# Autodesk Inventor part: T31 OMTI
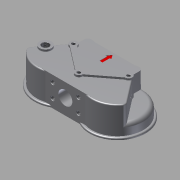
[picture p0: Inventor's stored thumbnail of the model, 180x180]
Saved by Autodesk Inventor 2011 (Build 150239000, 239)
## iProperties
Created: 2014-12
Part Number: T31 OMTI
Document SubType Name: Modeling
Designer: Храмов
Density: 1 g/cm^3
Author: Храмов
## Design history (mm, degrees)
sketch "Эскиз1"
  geometry: L1 (0, 0)-(150, 0); L2 (20.273, 67)-(129.727, 67); L3 (129.727, 67)-(129.727, -67); L4 (129.727, -67)-(20.273, -67); L5 (20.273, -67)-(20.273, 67); A1 r 70 centre (0, 0) between (-70, 0) and (20.273, 67); A2 r 70 centre (150, 0) between (220, 0) and (129.727, 67); 1 further point
  constraints: 10 end point, 4 point on circle, 2 centre point, 2 coincident, 2 horizontal, 2 parallel, 1 perpendicular
  dimensions: "d0" = 140 diameter of A1; "d1" = 140 diameter of A2; "d5" = 150 distance of A2.centre L1.start; "d6" = 67 distance between parallel lines of L2 L1; "d7" = 134 distance between parallel lines of L4 L2
extrude "Выдавливание1" new body sketch "Эскиз1" distance "d8" = 84; taper "d9" = 0 deg
sketch "Эскиз2"
  geometry: L1 (0, 84)-(109.454, 84) reference; L2 (54.727, 84)-(54.727, 42); L3 (54.727, 42)-(0, 42); L4 (0, 0)-(0, 84) reference; C1 r 19 at (54.727, 42); 1 further point
  constraints: 4 end point, 2 midpoint, 1 centre point, 1 horizontal, 1 vertical
  dimensions: "d10" = 38 diameter of C1
extrude "Выдавливание2" cut sketch "Эскиз2" distance "d11" = 200; taper "d12" = 0 deg
sketch "Эскиз3"
  geometry: L1 (19.727, 60.85)-(89.727, 60.85); L2 (89.727, 60.85)-(89.727, 23.15); L3 (89.727, 23.15)-(19.727, 23.15); L4 (19.727, 23.15)-(19.727, 60.85); L5 (54.727, 42)-(54.727, 60.85); L6 (54.727, 42)-(19.727, 42); C1 r 19 at (54.727, 42) reference; 5 further points
  constraints: 12 end point, 4 coincident, 2 horizontal, 2 midpoint, 2 parallel, 1 perpendicular, 1 vertical
  dimensions: "d13" = 70 distance of L1.start L1.end; "d14" = 37.7 distance of L1.end L2.end
hole "Отверстие1" sketch "Эскиз3" at (19.727, 60.85), (89.727, 60.85), (89.727, 23.15), (19.727, 23.15) diameter "d15" = 10.106; stored, may be unused: countersink angle "d19" = 82 deg, drill point angle "d21" = 118 deg; dims "d16" = 15, "d17" = 12, "d18" = 2, "d20" = 20
sketch "Эскиз4"
  geometry: L1 (89.727, -60.85)-(19.727, -60.85); L2 (19.727, -60.85)-(19.727, -23.15); L3 (19.727, -23.15)-(89.727, -23.15); L4 (89.727, -23.15)-(89.727, -60.85); C1 r 5.053 at (89.727, -60.85) reference; C2 r 5.053 at (19.727, -23.15) reference; 5 further points
  constraints: 8 end point, 4 coincident, 2 parallel, 1 horizontal, 1 perpendicular
hole "Отверстие2" sketch "Эскиз4" at (89.727, -60.85), (19.727, -60.85), (19.727, -23.15), (89.727, -23.15) diameter "d22" = 10.106; stored, may be unused: countersink angle "d26" = 82 deg, drill point angle "d28" = 118 deg; dims "d23" = 15, "d24" = 12, "d25" = 2, "d27" = 20
sketch "Эскиз5"
  geometry: C1 r 20 at (-150, 0); C2 r 20 at (0, 0); C3 r 25 at (-150, 0); C4 r 25 at (0, 0); A1 r 70 centre (0, 0) between (-20.273, -67) and (-20.273, 67) reference; A2 r 70 centre (-150, 0) between (-129.727, 67) and (-129.727, -67) reference
  constraints: 4 centre point, 4 coincident
  dimensions: "d29" = 40 diameter of C1; "d30" = 40 diameter of C2; "d31" = 50 diameter of C3; "d32" = 50 diameter of C4
extrude "Выдавливание3" join sketch "Эскиз5" distance "d33" = 30; taper "d34" = 0 deg
sketch "Эскиз6"
  geometry: C1 r 25 at (0, 0) reference; C2 r 25 at (-150, 0) reference; C3 r 76 at (-150, 0); C4 r 76 at (0, 0); A1 r 70 centre (0, 0) between (-20.273, -67) and (-20.273, 67) reference; A2 r 70 centre (-150, 0) between (-129.727, 67) and (-129.727, -67) reference
  constraints: 2 centre point, 2 coincident
  dimensions: "d35" = 152 diameter of C3; "d36" = 152 diameter of C4
extrude "Выдавливание4" join sketch "Эскиз6" distance "d37" = 5; taper "d38" = 0 deg
sketch "Эскиз7"
  geometry: L1 (129.727, -67)-(20.273, -67) reference; L2 (75, -67)-(75, -30); L3 (150, 30)-(0, 30); L4 (150, 0)-(0, 0); L5 (75, -30)-(75, 30); A1 r 70 centre (0, 0) between (20.273, 67) and (20.273, -67) reference; A2 r 70 centre (150, 0) between (129.727, -67) and (129.727, 67) reference; 2 further points
  constraints: 8 end point, 3 coincident, 2 midpoint, 2 perpendicular, 1 parallel, 1 vertical
  dimensions: "d39" = 30 distance from line of L4 L5.start; "d40" = 30 distance between parallel lines of L3 L4; "d41" = 150 distance of point (0, 30) point (150, 30)
hole "Отверстие3" sketch "Эскиз7" at (75, -30), (150, 30), (0, 30) diameter "d42" = 8.376; stored, may be unused: countersink angle "d46" = 82 deg, drill point angle "d48" = 118 deg; dims "d43" = 15, "d44" = 10, "d45" = 2, "d47" = 20
sketch "Эскиз8"
  geometry: L1 (20.273, 67)-(129.727, 67) reference; L2 (129.727, -67)-(20.273, -67) reference; L3 (75, -20)-(140, 30); L4 (75, -20)-(10, 30); L5 (150, 30)-(150, 20); L6 (0, 30)-(0, 20); L7 (75, -30)-(65, -30); L8 (75, -30)-(85, -30); L9 (65, -30)-(0, 20); L10 (85, -30)-(150, 20); L11 (75, -30)-(75, -20); L12 (0, 30)-(10, 30); L13 (0, 30)-(-10, 30); L14 (150, 30)-(160, 30); C1 r 5 at (0, 30) reference; C2 r 5 at (150, 30) reference; C3 r 5 at (75, -30) reference; C4 r 4.188 at (75, -30) reference; A1 r 70 centre (0, 0) between (20.273, 67) and (20.273, -67) reference; A2 r 70 centre (150, 0) between (129.727, -67) and (129.727, 67) reference; A3 r 10 centre (75, -30) between (65, -30) and (85, -30); A4 r 10 centre (150, 30) between (140, 30) and (150, 20); A5 r 10 centre (0, 30) between (0, 20) and (10, 30); 1 further point
  constraints: 24 end point, 9 point on circle, 4 equal length, 4 perpendicular, 3 centre point, 3 coincident, 1 vertical alignment, 1 other
  dimensions: "d49" = 20 diameter of A3; "d50" = 20 diameter of A5; "d51" = 20 diameter of A4
extrude "Выдавливание5" cut sketch "Эскиз8" distance "d52" = 5; taper "d53" = 0 deg
sketch "Эскиз9"
  geometry: L1 (140, 30)-(75, -20) reference; L2 (160, 30)-(210.354, -35.46); L3 (150, 30)-(160, 30); L4 (150, 40)-(150, 70); L5 (150, 30)-(150, 40); L6 (75, -30)-(75, 40); L7 (0, 40)-(0, 70); L8 (-10, 30)-(-60.354, -35.46); A1 r 10 centre (75, -30) between (65, -30) and (85, -30) reference; A2 r 10 centre (150, 30) between (150, 20) and (140, 30) reference; A3 r 70 centre (150, 0) between (129.727, -67) and (129.727, 67) reference; A4 r 70 centre (150, 0) between (129.727, -67) and (129.727, 67) reference; A5 r 10 centre (150, 30) between (160, 30) and (150, 40); A6 r 10 centre (0, 30) between (0, 40) and (-10, 30); A7 r 70 centre (0, 0) between (0, 70) and (-60.354, -35.46)
  constraints: 14 end point, 11 point on circle, 4 symmetric about line, 3 centre point, 1 collinear, 1 parallel, 1 perpendicular, 1 vertical
extrude "Выдавливание6" cut sketch "Эскиз9" distance "d54" = 45; taper "d55" = 0 deg
node "РабПлоскость1"
mirror "Зеркальное отражение1"
sketch "Эскиз10"
  geometry: L1 (129.727, -67)-(20.273, -67) reference; C1 r 16 at (-35, -11); C2 r 5 at (75, -30) reference
  constraints: 1 centre point
  dimensions: "d57" = 32 diameter of C1; "d58" = 56 distance from line of C1.centre L1; "d59" = 110 horizontal distance of C2.centre C1.centre
extrude "Выдавливание7" join sketch "Эскиз10" distance "d60" = 5; taper "d62" = 0 deg; dims "d61" = 50, "d63" = 0
sketch "Эскиз11"
  geometry: C1 r 16 at (0, 0) reference; 2 further points
  constraints: 1 coincident
hole "Отверстие4" sketch "Эскиз11" at (0, 0) diameter "d64" = 18.631; stored, may be unused: countersink angle "d68" = 82 deg, drill point angle "d70" = 118 deg; dims "d65" = 15, "d66" = 20, "d67" = 2, "d69" = 20
sketch "Эскиз12"
  geometry: L1 (45, 0)-(0, 0) reference; L2 (50, -3.903)-(50, 16.097) reference; 4 further points
  dimensions: "d71" = 17 distance from line of point (16, -17) L1; "d98" = 34 distance from line of point (16, -17) L2
hole "Отверстие5" sketch "Эскиз12" at (16, -17) diameter "d72" = 8.566; stored, may be unused: countersink angle "d76" = 82 deg, drill point angle "d78" = 118 deg; dims "d73" = 15, "d74" = 10, "d75" = 2, "d77" = 20
sketch "Эскиз13"
  geometry: L1 (0, 0)-(45, 0) reference; L2 (-5, 16.097)-(-5, -3.903) reference; 4 further points
  dimensions: "d79" = 17 distance from line of L1 point (29, -17); "d99" = 34 distance from line of point (29, -17) L2
hole "Отверстие6" sketch "Эскиз13" at (29, -17) diameter "d80" = 8.566; stored, may be unused: countersink angle "d84" = 82 deg, drill point angle "d86" = 118 deg; dims "d81" = 15, "d82" = 10, "d83" = 2, "d85" = 20
fillet "Сопряжение1" dims "d87" = 10
fillet "Сопряжение2" dims "d88" = 10
sketch "Эскиз14"
  geometry: L1 (20.273, 67)-(129.727, 67) reference; L2 (75, -20)-(75, 67); L3 (75, 30)-(71, 30); L4 (71, 30)-(71, 50); L5 (71, 50)-(67, 50); L6 (67, 50)-(75, 61.425); L7 (75, 30)-(79, 30); L8 (79, 30)-(79, 50); L9 (79, 50)-(83, 50); L10 (83, 50)-(75, 61.425)
  constraints: 18 end point, 3 symmetric about line, 2 perpendicular, 2 point on line, 1 midpoint, 1 parallel
  dimensions: "d89" = 4 distance between parallel lines of L2 L4; "d90" = 20 distance of L3.end L4.end; "d91" = 8 distance from line of L2 L5.end; "d92" = 55 deg angle of L5 L6; "d93" = 11.42518 distance from line of L5 L6.end (derived); "d94" = 37 distance from line of L2.end L3
extrude "Выдавливание8" cut sketch "Эскиз14" distance "d95" = 1; taper "d96" = 0 deg
fillet "Сопряжение3" dims "d97" = 3
fillet "Сопряжение4" dims "d100" = 3
node "Твердое тело1"
other parameters: "d56" = -75
